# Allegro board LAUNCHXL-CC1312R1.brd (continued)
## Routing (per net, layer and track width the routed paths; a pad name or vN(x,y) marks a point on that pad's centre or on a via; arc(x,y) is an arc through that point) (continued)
VBUS_DET: length 5
  TOP w0.15: R93.1 10.25,84.05 10.27,84.07 R92.1 10.23,84.24 v1(9.86,84.24) ; U5.12 v1(9.65,86.84)
  L3 w0.15: v1(9.86,84.24) 9.86,86.63 9.66,86.84 v1(9.65,86.84)
VDDC: length 16.2
  TOP w0.2: C45.1 2.25,92.25 C44.1 C43.1 2.45,94.6 U5.115 6.5,94.6 8.85,96.95 U5.87
VDDR: length 26.6
  TOP w0.3: U1.45 C19.1 24.15,50.65 v1(24.15,50.38) ; v1(24.2,48.9) C20.1 24.75,48.91 25.2,49.36 25.21,49.36 25.3,49.45 U1.48
  TOP w0.6: v1(26.75,61.2) v1(27.47,61.2) 27.47,60.4 C18.1 28.05,60.25 L10.2
  L3 w0.6: v1(24.2,48.9) 24.2,50.32 v1(24.15,50.38) 22.57,50.38 22.15,50.8 22.15,57.89 22.91,58.65 24.26,58.65 24.67,59.06 24.67,59.86 25.31,60.5 26.9,60.5 26.98,60.57 27.01,60.57 27.38,60.94 27.38,60.97 27.47,61.07 v1(27.47,61.2) v1(26.75,61.2)
VDDS: length 36.4
  TOP w0.3: U1.34 27.67,56.9 C17.1 C16.1 v1(25.3,57.15) ; U1.22 33.9,53.95 C14.1 33.95,54.25 v1(34.15,54.45) ; v1(33.35,48.85) 34.15,48.85 C12.1 34.24,48.75 33.79,49.2 33.79,49.21 33.55,49.45 U1.13 ; v1(24.02,52.22) 24.45,51.8 C15.1 24.45,51.6 24.99,51.6 25.14,51.45 U1.44 ; R1.2 v1(24.19,56.37)
  TOP w0.6: FL1.1 v1(24.15,57) 24.15,56.41
  L3 w0.3: 32.79,54.65 32.99,54.45 v1(34.15,54.45)
  L3 w0.6: 26.11,55.35 32.09,55.35 32.79,54.65 32.79,49.41 v1(33.35,48.85) ; 26.11,55.35 25.21,55.35 v1(24.19,56.37) 24.19,56.96 v1(24.15,57) 24.3,57.15 v1(25.3,57.15) ; 26.11,55.35 26.21,55.25 26.21,52.65 25.78,52.22 v1(24.02,52.22)
BP_RESET: length 16.8
  TOP w0.15: J2.11 48.45,56.84 48.45,71.14 48.61,71.3 R52.1
DCDC_SW: length 2.3
  TOP w0.3: L10.1 28.17,56.97 U1.33
DIO1: length 26
  TOP w0.15: v1(30.17,47.2) 29.89,47.49 29.71,47.49 29.17,48.02 U1.6
  BOTTOM w0.15: v1(30.17,47.2) 28.57,48.8 26.9,48.8 26.18,49.52 23.32,49.52 22.55,48.75 20.95,48.75 20.6,48.4 15.14,48.4 12.34,45.6 J1.20
DIO4_SCL: length 110.6
  TOP w0.15: U1.9 30.67,48.32 31.63,47.37 42,47.37 46.16,51.54 46.16,66.31 45.77,66.7 34.45,66.7 25.65,75.5 9.6,75.5 3.15,69.05 3.15,50.29 5.3,48.14 J1.17 5,46.81 5,45.55 R2.1
DIO5_SDA: length 110
  TOP w0.15: R3.1 4.29,43.64 4.37,43.64 J1.19 7.65,46.92 7.65,48.75 7,49.4 5.55,49.4 3.45,51.5 3.45,68.93 9.72,75.2 25.35,75.2 34.15,66.4 45.6,66.4 45.75,66.25 45.75,51.55 41.87,47.67 31.83,47.67 31.17,48.33 U1.10
DIO6_RLED: length 84.5
  TOP w0.15: U1.11 31.67,48.33 32.03,47.97 41.75,47.97 45.38,51.6 45.38,64.85 45.32,64.9 v1(45.32,65.3) ; v1(18.93,65.25) 19.21,65.53 v1(30.01,65.53)
  L3 w0.15: v1(18.93,65.25) 18.93,54.22 18.08,53.38 17.32,53.38 15.59,51.64 P6.2 ; v1(30.01,65.53) 29.72,65.25 29.72,63.59 29.97,63.35 34.87,63.35 36.32,64.8 41.12,64.8 41.62,65.3 v1(45.32,65.3) 45.94,65.92 J2.3
DIO7_GLED: length 79.2
  TOP w0.15: v1(44.8,65.9) 44.8,64.95 45.07,64.68 45.07,51.72 41.62,48.27 33,48.27 32.53,48.75 U1.12 ; v1(19.95,63.85) 20.23,64.13 29.83,64.13 v1(30.15,63.81)
  L3 w0.15: v1(30.15,63.81) 33.71,63.81 35.79,65.9 v1(44.8,65.9) 47.36,68.46 J2.1 ; P6.4 18.13,47.38 17.71,47.8 17.71,51.86 19.95,54.1 v1(19.95,63.85)
DIO8_MISO: length 36
  TOP w0.15: U4.2 44.35,40.68 44.62,40.95 v1(46.4,40.95) ; v1(44.65,52.16) v1(42.44,49.95) U1.14
  L3 w0.15: v1(46.4,40.95) 46.8,40.95 47.41,41.56 47.41,45.18 42.64,49.95 v1(42.44,49.95) ; J2.14 50.84,54.45 46.94,54.45 v1(44.65,52.16)
DIO9_MOSI: length 35.3
  TOP w0.15: U1.15 v1(40.99,50.45) 42.2,50.45 44.65,52.9 v1(44.65,57.05) ; U4.5 45.35,43.15 v1(45.5,43.3)
  L3 w0.15: v1(44.65,57.05) 50.78,57.05 J2.12 ; v1(40.99,50.45) 40.99,50.08 44.52,46.55 45.07,46.55 45.87,45.75 45.87,43.67 v1(45.5,43.3)
DIO10_SCLK: length 98.7
  TOP w0.15: U4.6 v1(44.85,44.25) ; J1.13 4.05,55.5 4.05,68.68 8.22,72.85 10.9,72.85 12.95,74.9 25.22,74.9 34.02,66.1 43.3,66.1 44.5,64.9 44.5,57.6 44.22,57.32 44.22,52.93 42.25,50.95 v1(39.83,50.95) U1.16
  L3 w0.15: v1(39.83,50.95) 39.83,49.57 43.1,46.3 43.92,46.3 44.85,45.37 v1(44.85,44.25)
DIO11_CS: length 29.5
  TOP w0.15: v1(43.85,62.25) 43.85,53.3 42,51.45 U1.17
  L3 w0.15: J2.6 50.79,62.1 44.4,62.1 44.25,62.25 v1(43.85,62.25)
DIO12: length 31.3
  TOP w0.15: U1.18 41.9,51.95 43.35,53.4 43.35,64.25 v1(43.8,64.7)
  L3 w0.15: J2.4 51.35,65.19 50.75,65.19 50.26,64.7 v1(43.8,64.7)
DIO13_BTN1: length 73.7
  TOP w0.15: R56.2 6.74,73.5 7.57,74.34 v1(7.63,74.34) ; U1.19 41.6,52.45 v1(42.5,53.35) 43,53.85 43,65.45 42.65,65.8 33.9,65.8 25.85,73.85 v1(14.9,73.85)
  L3 w0.15: v1(42.5,53.35) 44.35,51.5 45.28,51.5 45.73,51.95 50.8,51.95 J2.16 ; v1(14.9,73.85) 14.5,73.85 14.01,74.34 v1(7.63,74.34)
DIO14_BTN2: length 46
  TOP w0.15: J2.18 54.39,48.14 56.42,50.17 R55.2 ; U1.20 v1(41.43,52.95)
  L3 w0.15: J2.18 50.76,49.45 45.52,49.45 42.02,52.95 v1(41.43,52.95)
DIO15: length 22.5
  TOP w0.15: U1.21 v1(40.15,53.45)
  L3 w0.15: v1(40.15,53.45) 42.82,50.78 43.39,50.78 46.31,47.86 46.31,47.85 47.07,47.85 47.07,47.85 48.03,46.9 50.77,46.9 J2.20
DIO16_TDO: length 45.5
  TOP w0.15: R48.2 36.67,70.97 v1(36.67,71.7) ; U1.26 31.67,64.82 31.67,64.83 v1(31.67,65.45) ; P4.6 31.73,74.12 33,72.85 33,71.95 v1(33.95,71) ; CR8.5 39.25,75.7 v1(43.45,75.7) 43.73,75.7 44.09,76.06 P5.6
  L3 w0.15: v1(31.67,65.45) 31.67,65.85 31.67,65.86 31.67,69.5 33.18,71 v1(33.95,71) 35.97,71 v1(36.67,71.7)
  BOTTOM w0.15: v1(43.45,75.7) 43.45,75 42.95,74.5 38.1,74.5 36.67,73.07 v1(36.67,71.7)
DIO17_TDI: length 42.7
  TOP w0.15: v1(44.71,75.8) 45.36,76.45 P5.8 ; CR8.3 39.05,73.45 v1(38.95,73.35) ; P4.4 34.27,72.68 v1(35.2,71.75) R49.2 ; U1.27 v1(31.17,66.3)
  L3 w0.15: v1(31.17,66.3) 31.17,70.92 32.01,71.75 v1(35.2,71.75) 35.85,72.4 38,72.4 v1(38.95,73.35)
  BOTTOM w0.15: v1(38.95,73.35) 39.23,73.63 43.72,73.63 43.72,73.62 44.7,74.6 44.7,75.39 44.71,75.4 v1(44.71,75.8)
DIO19_CTS: length 25
  TOP w0.15: v1(30.17,60.79) U1.29
  L3 w0.15: J2.7 48.5,60.84 47.94,61.4 30.78,61.4 v1(30.17,60.79)
DIO20_FLASH_CS: length 61.1
  TOP w0.15: U4.1 42.9,40.25 R11.2 v1(42.15,40.1) ; v1(29.63,61.75) 29.63,60.47 29.85,60.25 29.85,56.57 29.67,56.4 U1.30
  L3 w0.15: J2.5 48.5,63.38 48.02,62.9 30.78,62.9 v1(29.63,61.75) 29.75,61.63 29.75,60 30.03,59.72 30.03,57.75 30.43,57.35 35.99,57.35 37.47,55.87 37.47,50.32 42.34,45.45 42.87,45.45 43.95,44.37 43.95,42.85 43.6,42.5 42.51,42.5 42.15,42.14 v1(42.15,40.1)
DIO21: length 62.1
  TOP w0.15: v1(29.23,56.57) 29.17,56.52 U1.31 ; v1(10.7,73.35) 8.3,73.35 3.75,68.8 3.75,53.26 J1.15
  L3 w0.15: v1(29.23,56.57) 29.23,56.98 29.38,57.13 29.38,61.16 29.2,61.34 29.2,68.44 25.84,71.8 v1(25.15,71.8)
  BOTTOM w0.15: v1(25.15,71.8) 24.5,71.8 23.8,71.1 12.95,71.1 v1(10.7,73.35)
DIO22: length 50.8
  TOP w0.15: J1.9 4.35,60.28 4.35,68.55 8.2,72.4 v1(9.95,72.4) ; U1.32 v1(28.67,56.47)
  L3 w0.15: v1(28.67,56.47) 28.67,56.78 28.35,57.1 28.35,67.66 v1(26.39,69.62)
  BOTTOM w0.15: v1(26.39,69.62) 12.72,69.62 v1(9.95,72.4)
DIO23_ANALOG: length 25.3
  TOP w0.15: U1.36 25.35,55.65 24.5,54.8 19.55,54.8 v1(10.15,64.2)
  L3 w0.15: v1(10.15,64.2) 9.7,64.65 7.6,64.65 J1.3
DIO24_ANALOG: length 20.4
  TOP w0.15: v1(18.3,54.6) 18.32,54.6 18.42,54.5 24.67,54.5 25.12,54.95 U1.37
  L3 w0.15: v1(18.3,54.6) 17.9,54.6 17.8,54.5 7.59,54.5 J1.11
DIO25_ANALOG: length 21.2
  TOP w0.15: J1.6 9.6,62.65 9.6,62.4 17.82,54.18 24.97,54.18 25.25,54.45 U1.38
DIO26_ANALOG: length 20
  TOP w0.15: J1.8 9.6,60.11 10.09,60.11 16.35,53.85 25.22,53.85 25.32,53.95 U1.39
DIO27_ANALOG: length 19.1
  TOP w0.15: U1.40 25.32,53.45 25.22,53.55 14.65,53.55 9.9,58.3 J1.10
DIO28_ANALOG: length 18.3
  TOP w0.15: J1.12 10.99,55.76 13.5,53.25 24.79,53.25 25.09,52.95 U1.41
DIO29_ANALOG: length 17.4
  TOP w0.15: J1.14 9.9,53.22 10.17,52.95 24.67,52.95 25.17,52.45 U1.42
DIO30/TCXO_VCC: length 8.1
  TOP w0.15: U1.43 25.17,51.95 24.47,52.65 19.75,52.65 19.35,52.25 R9.1 R8.2
DIO30_ANALOG: length 9.3
  TOP w0.15: R9.2 15.45,52.25 13.88,50.68 J1.16
ET_1V8: length 6.8
  TOP w0.3: U35.1 43.5,105.95 43.35,105.8 42.41,105.8 42.15,105.54 C128.1 42.1,104.95 C159.1 C158.1 39.4,104.75 U43.5
ET_3V3: length 52.6
  TOP w0.15: 44.69,100.7 44.69,100.04 44.25,99.6 U37.3
  TOP w0.3: C141.1 56.39,100.15 56.18,99.94 55.25,99.94 U41.5 55.7,100.41 C142.1 ; U42.4 U42.3 35.1,100.5 35.15,100.5 35.15,100.75 34.95,100.95 U42.4 ; U42.4 34.9,101.22 34.23,101.89 34.23,101.9 33.79,102.35 R132.2 33.75,102.37 C153.1 ; 44.69,100.7 44.69,101.41 C126.2 v1(45.76,101.9) ; 55.55,103.95 U40.2
  TOP w0.6: 38.6,101.2 C155.1 37.2,101.25 C154.1 35.2,101.25 U42.4 ; 38.6,101.2 38.25,101.55 v1(37.95,101.55) ; 38.6,101.2 C156.1 v1(41,101.1) ; FL5.1 35.15,111 FL6.2 35.19,108.81 v1(35.19,107.8) ; 55.55,103.95 U40.1 55.55,101.85 C142.1 v1(56.95,101.7)
  L3 w0.3: 45.79,102.5 45.76,102.48 v1(45.76,101.9)
  L3 w0.6: v1(41,101.1) 41.78,101.1 43.18,102.5 47.65,102.5 48.55,101.6 52.46,101.6 53.35,102.49 53.35,102.5 56.15,102.5 v1(56.95,101.7) ; v1(37.95,101.55) 37.95,107.08 37.23,107.8 v1(35.19,107.8)
ET_5V0: length 6.1
  TOP w0.3: FL3.1 40.05,92.85 C167.1 ; C168.1 39.97,91.52 C125.2 41.25,91.57 U36.7
  TOP w0.6: FL3.1 C168.1
ET_AVDD: length 22.6
  TOP w0.3: v1(49.19,103.85) 49.35,103.85 R98.1 ; 40.88,107.6 41.28,108 U35.32 ; U35.6 46,105.3 C120.1 46.3,104.95 v1(45.9,104.55)
  TOP w0.6: v1(42.23,106.95) 41.53,106.95 40.88,107.6 C119.1 39.85,107.6 C121.1 39.05,107.55 37.75,108.85 FL6.1 ; C122.1 49.25,103.79 v1(49.19,103.85)
  L3 w0.3: 47.27,104.64 47.18,104.55 v1(45.9,104.55)
  L3 w0.6: v1(42.23,106.95) 45.56,106.95 47.27,105.24 47.27,104.64 48.06,103.85 v1(49.19,103.85)
ET_BYPASS: length 60.8
  TOP w0.15: v1(12.3,102.15) 12.3,102.25 12.45,102.4 U5.78
  TOP w0.2: U33.8 51.3,87.45 v1(51.1,87.25) ; v1(55.84,88.25) 55.54,87.95 U33.4
  L3 w0.2: v1(55.84,88.25) 54.72,88.25 54.27,87.8 52.91,87.8 52.36,87.25 v1(51.1,87.25)
  BOTTOM w0.15: v1(12.3,102.15) 12.9,101.55 12.9,100.55 14.5,98.95 26.8,98.95 28.3,97.45 28.3,92.35 29,91.65 31.5,91.65 32.8,92.95 37.1,92.95 37.35,92.7 37.35,88.05 37.95,87.45 37.95,87.4 38.1,87.25 v1(51.1,87.25)
ET_CAL0: length 25.7
  TOP w0.15: R129.1 v1(32.85,96.95) ; U5.74 v1(14.05,102)
  TOP w0.2: U39.13 32.45,95.9 R129.1
  BOTTOM w0.15: v1(32.85,96.95) 32.4,96.95 32.2,97.15 32.2,99.3 31.85,99.65 30.4,99.65 28.97,101.07 14.52,101.07 14.05,101.55 v1(14.05,102)
ET_CAL1: length 27.9
  TOP w0.15: R128.1 30.2,92.15 30.05,92.3 30.05,92.43 v1(30.12,92.5) ; U5.73 14.45,102.5 14.6,102.35 14.6,101.25 14.6,101.25 v1(14.6,100.55)
  TOP w0.2: R128.1 30.65,93.15 30.9,93.4 U39.5
  BOTTOM w0.15: v1(14.6,100.55) 15,100.15 28.65,100.15 29.5,99.3 29.5,93.12 v1(30.12,92.5)
ET_CAL2: length 22
  TOP w0.15: U5.23 14.05,89.1 v1(14.2,89.25) ; v1(31.5,90.9) 31.95,91.35 R127.1
  TOP w0.2: R127.1 32.05,92.2 U39.6
  BOTTOM w0.15: v1(31.5,90.9) 30.85,90.9 30.3,90.35 19.75,90.35 18.65,89.25 v1(14.2,89.25)
ET_CALIBRATE: length 31.6
  TOP w0.15: U5.77 12.85,101.9 v1(11.95,101) ; U38.4 v1(31.3,90.2) 31,90.5 29.7,90.5 v1(29.25,90.95)
  BOTTOM w0.15: v1(11.95,101) 11.95,99.9 14,97.85 26.6,97.85 27.6,96.85 27.6,92.05 28.7,90.95 v1(29.25,90.95)
ET_DVDD: length 41.7
  TOP w0.3: 39.05,110.65 C117.1 ; 39.05,110.65 C116.1 40.88,110.65 41.03,110.5 U35.27 ; 39.05,110.65 39.4,110.3 R114.1 ; R119.1 v1(51.9,109.95) ; R96.1 v1(49.3,114.65)
  TOP w0.6: v1(36.67,112.3) 37,111.97 FL5.2 37.15,110.9 C117.1 ; v1(34.08,116.05) FL4.1 37.4,116.05 Y6.1
  L3 w0.3: 50.07,114.6 50.02,114.65 v1(49.3,114.65)
  L3 w0.6: v1(51.9,109.95) 50.95,109.95 50.07,110.83 50.07,115.67 49.29,116.45 43.95,116.45 42.15,114.65 37,114.65 ; 37,114.65 36.67,114.32 v1(36.67,112.3) ; 37,114.65 37,115.48 36.43,116.05 v1(34.08,116.05)
ET_FB: length 45.1
  TOP w0.15: U45.4 50.35,86 v1(50.5,85.85)
  TOP w0.3: C169.2 37.1,114.03 37.1,113.6 ; R138.1 37.1,113.6 ; 37.1,113.6 v1(37.6,113.6) ; U45.3 U45.4
  BOTTOM w0.15: v1(37.6,113.6) 38.4,112.8 47.3,112.8 48.25,111.85 48.25,107.1 50.7,104.65 50.7,103.95 52.35,102.3 52.35,100.8 52.65,100.5 52.65,87.15 51.35,85.85 v1(50.5,85.85)
ET_PM2: length 48.6
  TOP w0.15: 13.25,103.3 13.25,102.5 13.45,102.3 v1(13.45,102.15) ; R96.2 47.21,114.65 v1(47,114.44) U35.17
  BOTTOM w0.15: v1(47,114.44) 46.26,115.18 26.57,115.18 22.4,111 22.4,106.45 21.88,105.93 21.88,102.88 21.6,102.6 19.75,102.6 19.1,101.95 17.75,101.95 17.6,101.8 15.38,101.8 15.1,102.08 15.1,102.7 14.95,102.85 13.75,102.85 13.45,102.55 v1(13.45,102.15)
ET_PN3: length 56.3
  TOP w0.15: U5.110 v1(2.6,96.6)
  TOP w0.3: R114.2 40.72,110 U35.28 43.25,110 v1(43.45,109.8)
  L3 w0.15: v1(26.5,102.6) 26.5,97.5 26.65,97.35 v1(26.65,96.95)
  BOTTOM w0.15: v1(43.45,109.8) 42.97,109.32 35.17,109.32 32.05,106.2 32.05,103.3 31.65,102.9 26.8,102.9 v1(26.5,102.6) ; v1(26.65,96.95) 22.32,96.95 21.65,96.27 2.92,96.27 v1(2.6,96.6)
ET_SSICLK: length 59.1
  TOP w0.15: v1(5.32,93.12) 4.8,92.6 U5.120 ; U35.22 v1(44.5,111.9)
  L3 w0.15: v1(22.32,94.52) 24.06,94.52 25.35,95.81 25.35,101.69 v1(24.99,102.05)
  BOTTOM w0.15: v1(22.32,94.52) 22.04,94.24 6.44,94.24 v1(5.32,93.12) ; v1(44.5,111.9) 44.02,111.43 32.02,111.43 30.92,110.33 29.52,110.33 28.9,110.95 26.8,110.95 26.62,110.77 26.62,104.98 26.35,104.7 25.5,104.7 24.99,104.19 v1(24.99,102.05)
ET_SSIDAT0: length 61.5
  TOP w0.15: U5.123 4.6,91.4 4.75,91.25 v1(5.25,91.25) ; U35.21 v1(45,113.95)
  L3 w0.15: v1(24.23,101.8) 24.47,101.56 v1(24.47,95.8)
  BOTTOM w0.15: v1(45,113.95) 44.77,114.18 36.42,114.18 34.75,112.5 26.95,112.5 25.45,111 25.45,108.5 24.75,107.8 24.75,104.65 24.23,104.13 v1(24.23,101.8) ; v1(24.47,95.8) 24.47,94.02 22.9,92.45 15.15,92.45 14.8,92.1 6.65,92.1 5.8,91.25 v1(5.25,91.25)
ET_SSIDAT1: length 61.5
  TOP w0.15: v1(5.1,90.45) 4.55,91 3.75,91 ; U35.20 v1(45.5,111.9)
  L3 w0.15: v1(26.05,96.3) 26.05,102.19 v1(25.59,102.65)
  BOTTOM w0.15: v1(25.59,102.65) 25.59,103.55 25.89,103.85 28.75,103.85 29.65,104.75 29.65,108.9 29.85,109.1 32.6,109.1 33.8,110.3 43.9,110.3 v1(45.5,111.9) ; v1(5.1,90.45) 10.25,90.45 11.15,91.35 19.15,91.35 19.45,91.65 25.25,91.65 26.05,92.45 v1(26.05,96.3)
ET_SSIFSS: length 62.9
  TOP w0.15: U35.19 v1(46,114.05) ; U5.121 4.7,92.2 4.8,92.3 v1(5.7,92.3)
  L3 w0.15: v1(23.7,96.25) v1(23.7,102.55)
  BOTTOM w0.15: v1(23.7,96.25) 23.7,94.45 22.42,93.18 6.58,93.18 v1(5.7,92.3) ; v1(23.7,102.55) 23.25,103 23.25,108.6 24.55,109.9 24.55,111.6 26.55,113.6 35.1,113.6 36.2,114.7 45.35,114.7 v1(46,114.05)
ET_VDD: length 61.3
  TOP w0.3: 32.4,112.15 U46.3
  TOP w0.6: 31.3,107.7 v1(31.3,107.67) ; 31.3,107.7 32.15,107.7 C174.1 33.7,109.25 C173.1 33.7,111.86 33.41,112.15 ; 31.3,107.7 CR14.1 ; C172.1 35.03,112.58 R151.2 33.67,112.15 33.41,112.15 ; 33.41,112.15 U46.4 32.4,112.15
  TOP w1: v1(31.3,107.67) v1(31.3,106.75)
  L3 w1: P10.1 49.85,85.15 49.35,85.65 49.35,90.31 53.23,94.19 53.23,95.8 52.83,96.2 50.35,96.2 49.6,96.95 42.63,96.95 39.83,99.75 39.83,102.29 40.19,102.65 40.19,109.29 38.78,110.7 34.43,110.7 33.08,109.35 33.04,109.35 31.36,107.67 v1(31.3,107.67) v1(31.3,106.75)
ET_VREF: length 17
  TOP w0.3: 51.47,107.28 C146.1 ; 51.47,107.28 50.75,108 C127.1 U35.9 ; 51.47,107.28 v1(51.47,108.35) ; 51.25,104.9 U40.6 ; v1(50.8,102.75) 50.8,100.1 50.25,99.55 R121.1
  TOP w0.6: 51.25,104.9 U40.5 51.25,106.9 C146.1
  L3 w0.3: v1(50.8,102.75) 51.47,103.42 v1(51.47,108.35)
IRSTN: length 24.6
  TOP w0.15: v1(19.69,105) 19.9,104.79 R20.2
  BOTTOM w0.15: P8.10 4.05,106.93 4.05,108.3 6.02,110.27 6.7,110.27 7.02,109.95 8.82,109.95 9.42,109.35 9.42,106.32 11.95,103.8 18.49,103.8 v1(19.69,105)
ITCK: length 13
  TOP w0.15: U5.100 2.85,100.6 2.59,100.86 1.44,100.86 v1(1.05,101.25)
  BOTTOM w0.15: P8.4 1.06,110.01 0.76,109.71 0.76,101.54 v1(1.05,101.25)
ITDI: length 14.3
  TOP w0.15: U5.98 2.9,101.4 2.5,101.8 v1(2.2,101.8)
  L3 w0.15: v1(3.63,103.95) 4.51,104.83 4.51,109.6 v1(5.31,110.4)
  BOTTOM w0.15: v1(5.31,110.4) 4.08,109.17 3.75,109.17 P8.8 ; v1(3.63,103.95) 2.2,102.52 v1(2.2,101.8)
ITDO: length 17.6
  TOP w0.15: v1(2.65,112.85) 2.05,113.45 1.35,113.45 0.85,112.95 0.85,103.55 1.25,103.15 2.5,103.15 2.8,102.85 2.8,102.1 3.1,101.8 U5.97
  BOTTOM w0.15: v1(2.65,112.85) 2.65,111.95 P8.6
ITMS: length 9.1
  TOP w0.15: 3.75,101 2.88,101 2.64,101.24 1.96,101.24 1.55,101.65 v1(1.55,102)
  BOTTOM w0.15: P8.2 1.45,107.47 1.3,107.32 1.3,102.65 1.55,102.4 v1(1.55,102)
LP_RESET: length 17.1
  TOP w0.15: R51.1 50.8,70.55 51.4,69.95 53.3,69.95 54,69.25 54,58.75 53.55,58.3 J2.10
LS_VDD: length 60.1
  TOP w0.15: v1(25.59,85.35) 25.1,84.86 C74.1 24.85,85.1 U10.2 ; U8.2 21,85.1 C70.1 21.1,85.01 v1(21.64,85.56) ; C72.1 28.95,85.1 U9.2
  TOP w0.2: v1(51.15,86.5) 51.15,86.57 51.53,86.95 U33.9 ; U33.3 v1(55.8,87.45)
  TOP w0.3: v1(30.5,84.35) 29.85,85 C72.1 29.05,85.35 v1(28.9,85.5) ; v1(38.51,86.2) 38.51,85.36 CR7.8
  TOP w0.6: P7.1 v1(45.71,88.34)
  L3 w0.15: v1(21.64,85.56) 21.93,85.84 25.1,85.84 v1(25.59,85.35) 25.99,85.75 28.25,85.75 28.5,85.5 v1(28.9,85.5)
  L3 w0.3: v1(30.5,84.35) 32.12,84.35 32.89,85.12 37.44,85.12 v1(38.51,86.2)
  L3 w0.6: v1(38.51,86.2) 38.76,85.95 44.31,85.95 ; 51.76,86.05 51.31,86.5 v1(51.15,86.5) ; 54.96,87.05 55.36,87.45 v1(55.8,87.45) ; P10.2 45.2,81.16 44.31,82.05 44.31,85.95 ; 44.31,85.95 44.46,85.95 45.71,87.2 v1(45.71,88.34)
  L3 w1: 53.31,85.55 54.46,85.55 54.96,86.05 54.96,87.05 ; 53.31,85.55 52.26,85.55 51.76,86.05 ; 53.31,85.55 53.41,85.45 53.41,83.27 51.3,81.16 P10.2
SW_VDD: length 59.6
  TOP w0.2: U39.14 32.05,96 C140.1 ; U33.1 55.45,86.45 C114.1
  TOP w0.3: 32.8,89.02 32.8,89.15 C139.1 ; 32.8,89.02 33.13,89.02 33.39,88.76 v1(33.39,88.15) ; 32.8,89.02 U38.1 ; v1(46.91,84.75) 46.98,84.82 54.77,84.82 55.6,85.65 C114.1 ; U45.5 49.35,87.3 48.88,87.78 C170.2 48.34,88.4 48.14,88.2 v1(47.51,88.2) ; C140.1 v1(31,96.25)
  TOP w0.6: v1(36.43,85.78) v1(36.43,86.46) 36.43,87.1 ; 36.43,87.1 C163.1 37,88.01 U44.5 38.74,88.66 C162.1 ; 36.43,87.1 R134.2
  L3 w0.3: v1(47.51,88.2) 46.91,88.2
  L3 w0.6: v1(33.95,91.7) 33.95,92.33 33.55,92.73 33.55,94.71 31.96,96.3 31.05,96.3 v1(31,96.25) ; v1(36.43,85.78) v1(36.43,86.46) ; v1(36.43,86.46) v1(34.11,86.46) 33.4,87.17 33.4,87.51 33.39,87.52 v1(33.39,88.15) ; v1(36.43,86.46) 36.43,87.59 37.99,89.15 42.4,89.15 43.35,90.1 46.31,90.1 46.91,89.5 v1(46.91,84.75)
  BOTTOM w0.6: v1(34.11,86.46) 34.11,87.09 34.43,87.4 34.43,91.22 v1(33.95,91.7)
TARGET_VDD: length 22.8
  TOP w0.3: U38.5 30.8,88.95 30.4,89.35 v1(30.4,89.5) v1(30.4,89.9)
  L3 w1: v1(30.4,89.9) 30.35,89.85 30.35,85.71 29.05,84.41 21.69,84.41 21.68,84.4 17.4,84.4 16.49,83.49 P4.17
TCXO_OUTPUT: length 1.2
  TOP w0.32: R7.1 20.49,47.26 C25.2
USB1V8: length 15
  TOP w0.15: C85.2 14.8,106.32 14.53,106.6 v1(14.45,106.6) 13.4,106.6 ; U15.15 v1(6.7,106.6) C84.1 ; 13.4,106.6 U15.26 ; 13.4,106.6 C83.1
  L3 w0.15: v1(14.45,106.6) 14.03,106.18 14.03,104.67 13.71,104.35 11.98,104.35 10.23,106.1 7.2,106.1 v1(6.7,106.6)
USB_VBUS: length 13.1
  TOP w0.3: v1(10.05,112.65) 10.16,112.54 10.5,112.54 CR6.6
  TOP w0.32: v1(15.95,110.6) 15.9,110.65 R154.1 ; U47.3 U47.4
  TOP w0.4: J6.1 v1(10.05,113.05) v1(10.05,112.65)
  TOP w0.6: C106.1 v1(13.5,111.6) ; 15.95,110.15 v1(15.95,110.6) U47.4
  L3 w0.15: v1(13.5,111.6) 13.53,111.6
  L3 w0.6: v1(15.95,110.1) v1(15.95,110.6) 14.53,110.6 13.13,112 10.47,112 10.05,112.42 v1(10.05,112.65) v1(10.05,113.05)
USBA1V8: length 3.2
  TOP w0.15: 14.95,108.76 C86.2 14.52,108.35 13.65,108.35 13.4,108.1 C87.1 13.2,108.1 U15.29
USBCLK: length 7.8
  TOP w0.15: U5.92 6.85,104.25 6.63,104.48 5.67,104.48 4.61,105.54 4.61,106.68 5.03,107.1 U15.14
USBD0: length 2.2
  TOP w0.15: U5.81 11.25,104.35 11.6,104.7 U15.24
USBD1: length 2.2
  TOP w0.15: U5.82 10.85,104.37 11.1,104.62 U15.23
USBD2: length 2.2
  TOP w0.15: U15.22 10.6,104.55 10.45,104.4 U5.83
USBD3: length 2.1
  TOP w0.15: U5.84 10.05,104.5 10.1,104.55 U15.21
USBD4: length 2.1
  TOP w0.15: U5.85 9.65,104.5 9.6,104.55 U15.20
USBD5: length 2.2
  TOP w0.15: U5.86 9.25,104.4 9.1,104.55 U15.19
USBD6: length 11.3
  TOP w0.15: U5.106 7.25,98.2 7.76,98.71 7.76,100.21 v1(8.05,100.5) ; v1(8.6,104.55) U15.18
  BOTTOM w0.15: v1(8.6,104.55) 8.6,101.05 v1(8.05,100.5)
USBD7: length 10.8
  TOP w0.15: U5.105 6.15,98.6 6.15,98.6 6.75,98.6 v1(7.05,98.9) ; U15.17 8.1,104.7 7.95,104.55 v1(7.67,104.55)
  BOTTOM w0.15: v1(7.67,104.55) 6.75,103.63 6.75,100.3 7.05,100 v1(7.05,98.9)
USBDIR: length 12.6
  TOP w0.15: v1(5.85,99.03) 5.82,99 U5.104 ; U15.12 6.4,108.1 6.37,108.07 v1(6.33,108.07)
  BOTTOM w0.15: v1(5.85,99.03) 5.85,100.3 5.62,100.52 5.62,107.37 v1(6.33,108.07)
USBDM: length 9.3
  TOP w0.15: CR6.5 11.2,112.6 v1(10.85,112.95) 10.7,113.1 J6.2 ; U15.8 7.62,110.3 v1(7.47,110.45)
  L3 w0.15: v1(7.47,110.45) 7.47,112.62 8.59,113.75 10.68,113.75 10.83,113.6 10.83,112.97 v1(10.85,112.95)
USBDP: length 12.3
  TOP w0.15: U15.7 8.6,110.93 8.33,111.2 v1(6.91,111.2) ; CR6.4 11.7,112.8 v1(11.5,113) 11.35,113.15 J6.3
  L3 w0.15: v1(11.5,113) 11.5,114 11.35,114.15 7.91,114.15 7.03,113.27 7.03,111.5 6.91,111.38 v1(6.91,111.2)
USBNXT: length 14.6
  TOP w0.15: v1(5.35,99.7) 5.05,99.4 U5.103 ; U15.11 7.09,108.6 6.39,109.3 v1(5.65,109.3)
  BOTTOM w0.15: v1(5.65,109.3) 4.4,108.05 4.4,100.1 4.8,99.7 v1(5.35,99.7)
USBSTP: length 5.3
  TOP w0.15: U5.91 v1(7.25,105.25) ; v1(6.65,107.52) 6.67,107.52 6.75,107.6 U15.13
  BOTTOM w0.15: v1(7.25,105.25) 7.25,106.93 v1(6.65,107.52)
VCM: length 18.9
  TOP w0.3: v1(51.7,100.25) 52,99.95 U41.1 ; v1(47.39,95.3) 47.39,95.94 R109.2 46.7,95.95 R100.1 ; v1(49.1,98.17) 49.12,98.2 R111.2 ; v1(55.83,97.1) R131.1
  L3 w0.3: 52.35,98.17 52.95,98.77 U41.1 52.65,100.25 v1(51.7,100.25) ; 52.35,98.17 54.76,98.17 v1(55.83,97.1) ; 52.35,98.17 v1(49.1,98.17)
  BOTTOM w0.3: v1(47.39,95.3) 47.39,96.46 v1(49.1,98.17)
WMCU_RESET: length 70
  TOP w0.15: R51.2 R52.2 49.31,75.5 47.47,77.33 ; v1(37.99,73.47) 38.55,74.03 CR8.2 ; 47.47,77.33 47.21,77.6 P5.10 ; 47.47,77.33 v1(47.47,77.32) ; v1(20.95,66.95) 21.2,67.2 24.75,67.2 v1(24.95,67.4) ; v1(21.45,55.5) C52.1 22.25,55.45 R1.1 24.3,55.45 25.2,56.35 27.05,56.35 27.17,56.22 U1.35
  L3 w0.15: v1(24.95,67.4) 24.95,70.85 24.11,71.69 v1(24.11,72.81) 24.77,73.47 v1(37.99,73.47) ; v1(21.45,55.5) 21.37,55.5 20.95,55.92 v1(20.95,66.95)
  BOTTOM w0.15: v1(47.47,77.32) 47.47,76.03 44.1,72.65 38.35,72.65 37.99,73.01 v1(37.99,73.47) ; v1(24.11,72.81) P4.12
WMCU_RXD: length 95.4
  TOP w0.15: U1.7 29.67,48.1 29.99,47.78 30.21,47.78 31.23,46.77 42.25,46.77 46.81,51.34 46.81,66.51 46.02,67.3 35.15,67.3 26.63,75.81 19.53,75.81 19.03,76.32 P4.16 ; v1(13.71,73.75) 13.2,73.75 10.5,71.05 10.5,67.95 9.95,67.4 6,67.4 5.05,66.45 5.05,64.66 J1.5
  BOTTOM w0.15: P4.16 19.03,77.59 19.05,77.57 19.05,76.3 17.39,74.65 14.6,74.65 v1(13.71,73.75)
WMCU_SWO: length 47.1
  TOP w0.15: v1(30.68,66.9) v1(30.68,59.7) 30.67,59.69 U1.28 ; v1(34.95,72.7) 34.95,76.76 P4.2
  L3 w0.15: v1(30.68,59.7) 46.7,59.7 48.1,58.3 J2.9 ; v1(34.95,72.7) 31.24,72.7 30.68,72.14 v1(30.68,66.9)
WMCU_TCK: length 49.4
  TOP w0.15: v1(39.65,79.45) 42.7,79.45 42.82,79.33 P5.4 ; CR8.6 38.55,76.5 38.66,76.61 39.38,76.61 v1(39.65,76.34) v1(39.67,76.32) ; v1(38.11,71.65) 38.1,71.64 R47.2 ; U1.25 v1(32.17,64.7)
  L3 w0.15: v1(32.17,64.7) 32.17,68.56 33.87,70.25 36.71,70.25 v1(38.11,71.65) 38.65,71.65 39.55,72.55 39.55,76.25 v1(39.65,76.34) v1(39.67,76.32)
  BOTTOM w0.15: v1(39.65,79.45) v1(39.65,76.34) 39.41,76.1 29.35,76.1 29.19,76.26 P4.8
WMCU_TMS: length 48
  TOP w0.15: v1(40.19,71.72) 40.19,71.57 39.57,70.95 R46.2 ; v1(40.6,77.55) 40.65,77.6 ; 40.65,77.6 38.8,77.6 38.05,76.85 CR8.7 37.3,75.9 v1(36.75,75.35) ; 40.65,77.6 P5.2 ; U1.24 v1(32.88,64.55)
  L3 w0.15: v1(32.88,64.55) 32.88,67.85 34.57,69.55 38.02,69.55 v1(40.19,71.72) 40.6,72.13 v1(40.6,77.55)
  BOTTOM w0.15: P4.10 26.65,76.45 27.75,75.35 v1(36.75,75.35)
WMCU_TXD: length 96.1
  TOP w0.15: v1(23.4,74.35) 13.1,74.35 10.65,71.9 8.12,71.9 4.65,68.43 4.65,62.52 J1.7 ; v1(27.1,74.7) 34.8,67 45.9,67 46.51,66.38 46.51,51.47 42.12,47.07 31.35,47.07 30.17,48.25 U1.8
  L3 w0.15: v1(23.4,74.35) 23.75,74.7 v1(27.1,74.7)
  BOTTOM w0.15: P4.14 21.57,74.81 22.03,74.35 v1(23.4,74.35)
WMCU_VDD: length 189.7
  TOP w0.3: v1(43.1,44) 43.43,43.67 R60.2 ; CR8.8 37.55,75.15 37,74.6 v1(37,74.45) ; 2.7,43.25 v1(2.1,43.84) ; 2.7,43.25 3.3,42.65 R3.2 ; 2.7,43.25 R2.2 2.7,43.25 ; R59.2 42.8,39.15 R11.1 41.75,39.2 v1(41.45,39.5) R12.2
  TOP w0.6: P5.1 v1(41.55,71.8)
  TOP w1: v1(22.9,61.45) v1(22.9,60.65) 22.9,60.55 FL1.2
  L3 w0.3: P1.1 52.03,35.4 50.75,35.4 49.83,36.32 49.83,38.05 48.38,39.5 v1(41.45,39.5) 41.44,39.5 40.99,39.95 40.99,43.19 41.8,44 v1(43.1,44) ; J1.1 4.25,68.46 1.54,65.75 1.54,44.4 v1(2.1,43.84)
  L3 w0.6: v1(41.55,71.8) 41.55,71.98 42.15,72.58 42.15,78.51 42.19,78.55 ; 21.59,76.18 21.47,76.3 ; v1(37,74.45) 37.38,74.45 37.83,74.9 37.83,75.98 37.51,76.3
  L3 w1: P4.18 16.49,76.88 17.07,76.3 ; J1.1 6.33,74.72 ; 6.33,74.72 7.91,76.3 17.07,76.3 ; 6.33,74.72 6.31,74.7 ; 17.07,76.3 37.51,76.3 39.76,78.55 49.78,78.55 P10.3 52.2,78.62 52.23,78.65 52.37,78.65 54.07,76.95 54.07,71.02 56.03,69.06 56.03,37.84 53.61,35.42 P1.1 ; 21.59,76.18 21.59,71.75 22.9,70.44 v1(22.9,61.45) v1(22.9,60.65)
XDS_RESET: length 11.5
  TOP w0.15: v1(23.19,87.5) 23.2,87.5 23.46,87.24 U10.6 23.46,84.85 23.61,84.7 U10.1 ; U5.40 21.15,92.2 R58.1 22.3,92.1 22.45,91.95 v1(22.45,89.9)
  BOTTOM w0.15: v1(23.19,87.5) 22.45,88.24 v1(22.45,89.9)
XDS_RESET_LS: length 58.3
  TOP w0.15: 40.63,82.68 v1(39.93,82.68) ; v1(21.53,114.98) R57.2 ; 37.05,84.6 36.91,84.46 v1(36.91,84.2) ; 37.05,84.6 35.12,84.6 34.75,84.23 v1(34.3,84.23) ; 37.05,84.6 CR7.2 ; v1(25.27,89.93) 24.4,90.8 24.4,94.09 v1(22.99,95.5) ; U10.15 23.46,82.99 v1(23.7,82.75) 24.11,82.34 P4.11
  L3 w0.15: v1(23.7,82.75) 24,83.05 31.54,83.05 32.71,84.23 v1(34.3,84.23) ; v1(21.53,114.98) 21.93,114.98 22.99,113.92 v1(22.99,95.5) ; v1(36.91,84.2) 37.19,83.91 38.7,83.91 v1(39.93,82.68)
  BOTTOM w0.15: v1(23.7,82.75) 23.7,86.75 25.56,88.61 25.56,89.64 v1(25.27,89.93)
XDS_RX: length 3.1
  TOP w0.15: U5.33 19.15,87.33 18.66,86.84 U8.8
XDS_RX_LS: length 9
  TOP w0.15: U8.13 18.66,83.41 18.95,83.12 R61.2 18.95,83.03 17.75,81.82 17.75,80.2 18.05,79.9 20.31,79.9 P4.13
XDS_SWO: length 7.2
  TOP w0.15: U5.25 14.85,88.75 15,88.9 17.9,88.9 18.05,88.75 18.05,86.3 U8.9
XDS_SWO_LS: length 26.7
  TOP w0.15: 35.6,83.69 35.95,83.69 36.81,82.83 P4.1 ; 35.6,83.69 v1(33.44,83.69) ; 35.6,83.69 35.57,83.66 R62.2 ; v1(17.45,82.21) 17.3,82.21 16.9,82.61 16.9,84.35 17.25,84.7 U8.12
  L3 w0.15: v1(33.44,83.69) 32.45,82.7 24.53,82.7 24.04,82.21 v1(17.45,82.21)
XDS_TCK: length 11.7
  TOP w0.15: v1(23.25,89.2) 23.53,89.49 26.82,89.49 27.46,88.84 U9.6 ; v1(20.65,89.2) 20.65,89.65 20.1,90.2 U5.35
  L3 w0.15: v1(23.25,89.2) v1(20.65,89.2)
XDS_TCK_LS: length 29
  TOP w0.15: U9.15 27.46,83.42 27.89,82.99 28.85,82.99 29.19,82.64 P4.7 ; v1(44.44,80.5) P7.4 44.44,83.83 43.67,84.6 CR7.6
  L3 w0.15: P4.7 30.44,79.91 38.89,79.91 39.28,80.3 43.84,80.3 44.04,80.5 v1(44.44,80.5)
XDS_TDI: length 10.5
  TOP w0.15: U9.7 27.06,87.44 25.95,88.55 23.05,88.55 20.2,91.4 U5.38
XDS_TDI_LS: length 25.9
  TOP w0.15: P4.3 32.78,82.65 31.2,82.65 30.5,81.95 30.5,80.5 29.9,79.9 28.5,79.9 27.95,80.45 27.95,82.5 27.06,83.39 U9.14 ; P7.8 41.9,81.05 41.7,80.85 v1(41.7,80.83) ; v1(37.75,83.2) CR7.3
  L3 w0.15: P4.3 35,81.89 35,82.95 35.25,83.2 v1(37.75,83.2) 40.12,80.83 v1(41.7,80.83)
XDS_TDO: length 9.9
  TOP w0.15: 19.15,91 20.18,91 23.17,88 25.2,88 26.25,86.95 26.25,86.1 U9.9
XDS_TDO_LS: length 29
  TOP w0.15: v1(25.59,82.05) 25.59,84.37 25.92,84.7 U9.12 ; P7.6 v1(43.17,80.88) 43.17,80.31 R63.2 ; v1(39.83,83.8) 39.53,84.1 CR7.5
  L3 w0.15: v1(25.59,82.05) 26.06,82.05 26.29,82.29 30.61,82.29 P4.5 34.12,83.55 34.59,83.55 35.66,84.62 39.01,84.62 v1(39.83,83.8) 42.79,83.8 43.19,83.4 43.19,80.9 v1(43.17,80.88)
XDS_TMS: length 6.1
  TOP w0.15: U5.36 20.15,90.6 22.66,88.09 U10.8
XDS_TMS_DIR: length 13.2
  TOP w0.15: U10.5 v1(23.86,87.55) ; v1(18.55,87.6) 18.55,88.68 18.02,89.2 14.8,89.2 14.45,88.85 U5.24
  L3 w0.15: v1(23.86,87.55) 23.42,87.99 18.94,87.99 v1(18.55,87.6)
XDS_TMS_LS: length 34.7
  TOP w0.15: U10.13 22.66,83.55 22.81,83.4 22.81,80.49 23.4,79.9 25.39,79.9 P4.9 ; 45.72,82.67 P7.2 ; CR7.7 v1(39.9,85.1)
  TOP w0.3: R65.2 46.2,83.17 P7.2 45.71,83.51 v1(46.35,84.15)
  BOTTOM w0.3: v1(46.35,84.15) 45.4,85.1 v1(39.9,85.1) 33.9,85.1 31.55,82.75 26.95,82.75 26.65,82.45 P4.9
XDS_TX: length 4.5
  TOP w0.15: U8.6 19.46,88.51 20.15,89.2 20.15,89.65 20,89.8 U5.34
XDS_TX_LS: length 3.1
  TOP w0.15: P4.15 19.03,82.28 19.46,82.71 U8.15
XDS_VDD: length 189.2
  TOP w0.15: U5.113 2.85,95.4 2.7,95.55 C3.1 ; v1(6.25,105.17) C78.1 6.63,105.7 7.03,106.1 U15.16 ; U5.69 16.05,104.5 C38.1 ; 8.07,111.8 v1(8.07,112.3) ; 8.07,111.8 R83.1 8.51,111.54 9.1,110.95 U15.6 ; 8.07,111.8 C80.1 ; U5.52 20.25,97 C39.1 U5.51 ; C6.1 13.35,105.25 12.99,105.25 12.9,105.16 12.9,105.2 ; C73.1 28.82,85.93 28.72,85.93 28.7,85.9 U9.4 U9.3 ; v1(2.23,99.62) C4.1 2.69,100.2 U5.101 ; 12.9,105.2 12.9,105.9 12.7,106.1 U15.25 ; 12.9,105.2 v1(12.9,105.2) 12.05,104.36 U5.79 ; R17.2 19,105.05 v1(18.75,105.3) ; U5.122 v1(4.85,91.8) ; 19.15,95 20.15,95 v1(20.25,94.9) ; v1(7.35,102.05) 7.65,102.35 U5.90 ; C71.1 20.85,85.9 U8.4 U8.3 ; U5.26 15.25,86.85 15.29,86.81 15.29,86.79 15.69,86.4 C2.1 16.05,86.75 U5.28 ; U15.31 13.05,109.1 ; 13.05,109.1 v1(13.3,109.36) ; 13.05,109.1 13.1,109.1 C79.1 13.2,108.6 U15.30 ; R58.2 21.25,91.19 20.64,91.8 U5.39 ; U5.16 v1(11.25,86.84) ; C75.1 25.05,85.9 U10.4 U10.3 ; U5.7 7.65,86.5 C42.1 8.05,86.7 U5.8
  TOP w0.2: v1(1.85,96.15) 1.85,96 2.19,95.66 C3.1 ; v1(24.63,109.15) 24.6,109.12 24.6,108.5 ; C47.1 24.23,103.42 R33.2 v1(24.23,104.93)
  TOP w0.3: C73.1 28.9,86.15 v1(28.4,86.65) ; C71.1 21.45,86.1 v1(21.7,86.35) ; C42.1 C7.1 6.45,86.4 v1(6.15,86.1) ; R18.2 v1(8.8,84.9) ; C40.1 21.15,96.6 ; 21.15,96.6 C39.1 ; 21.15,96.6 21.15,96.88 21.15,96.89 v1(21.15,97.08) ; 21.85,101.95 v1(22.3,101.95) ; 21.85,101.95 R27.1 ; 21.85,101.95 R39.1 ; 25.45,108.5 U7.3 ; C38.1 v1(15.95,105.1) ; R58.2 v1(21.73,91.18) ; R31.2 v1(18.75,105.3) ; C2.1 v1(15.7,85.8) ; C75.1 25.45,85.95 v1(25.7,86.2)
  TOP w0.6: 25.45,108.5 U7.4 C49.1 C113.1 v1(21.55,108.5) v1(21,108.5)
  L3 w0.15: 7.59,103.3 7.67,103.22 ; 7.37,102.05 v1(7.35,102.05) ; 6.25,103.32 6.23,103.3
  L3 w0.2: v1(24.63,109.15) 24.63,105.33 v1(24.23,104.93)
  L3 w0.3: v1(11.25,86.84) 11.25,88.15 ; v1(1.85,96.15) 1.85,95.97 2.27,95.55 3.59,95.55 3.75,95.39 ; v1(18.75,105.3) 17,105.3 16.95,105.25 ; 25.71,86.79 25.7,86.77 v1(25.7,86.2) ; 19.39,91.2 19.41,91.18 v1(21.73,91.18) ; v1(15.7,85.8) 15.7,88.12 15.67,88.15 ; v1(20.25,94.9) 19.39,94.9 ; 7.37,102.05 7.67,102.35 7.67,103.22 ; v1(8.8,84.9) 8.8,88.14 8.79,88.15 ; v1(6.25,105.17) 6.25,103.32 ; v1(15.95,105.1) 15.95,103.3 ; v1(22.3,101.95) 19.39,101.95 ; v1(8.07,112.3) 8.07,112.27 9.19,111.15 9.19,110.07 9.31,109.95 ; v1(21.7,86.35) 21.7,86.77 21.71,86.79 ; v1(21.15,97.08) 20.67,96.6 19.39,96.6 ; 3.75,102.58 2.74,102.58 1.82,103.5 1.82,105.48 v1(1.85,105.5)
  L3 w0.6: 12.91,107.25 12.9,107.24 v1(12.9,105.2) ; 12.91,107.25 14.95,107.25 16.2,108.5 16.95,108.5 ; 12.91,107.25 12.91,108.96 ; 17.55,88.15 7,88.15 6.91,88.06 ; 17.55,88.15 17.99,88.15 19.39,89.55 19.39,91.2 ; 17.55,88.15 17.55,87.21 17.97,86.79 28.26,86.79 v1(28.4,86.65) ; 16.95,108.5 v1(21,108.5) v1(21.55,108.5) ; 16.95,108.5 16.95,103.3 ; 3.75,91.8 3.75,89.5 5.19,88.06 6.91,88.06 ; 3.75,91.8 3.75,99.63 ; 3.75,91.8 3.76,91.8 v1(4.85,91.8) ; v1(6.15,86.1) 6.15,87.3 6.91,88.06 ; 9.31,109.95 12.03,109.95 12.91,109.07 12.91,108.96 ; 16.95,103.3 18.72,103.3 19.39,102.63 19.39,94.9 ; 16.95,103.3 4.47,103.3 3.75,102.58 3.75,99.63 ; v1(2.23,99.62) 3.74,99.62 3.75,99.63 ; 12.91,108.96 v1(13.3,109.36)
  BOTTOM w0.3: P8.1 1.85,106 v1(1.85,105.5)
N949215: length 9.6
  TOP w0.15: 20.8,103.4 R21.1 ; 20.8,103.4 R20.1 R17.1 ; 20.8,103.4 v1(21.2,103.4) ; U5.70 v1(15.65,102.24)
  BOTTOM w0.15: v1(15.65,102.24) 15.65,102.64 15.91,102.9 18.5,102.9 R17.1 v1(21.2,103.4)
N949243: length 2.1
  TOP w0.15: R30.1 21.04,99.7 20.54,100.2 U5.60
N949263: length 3.1
  TOP w0.2: R34.2 25.2,103.38 C47.2 25.15,103.42 R33.1 U7.5
N949375: length 2.3
  TOP w0.15: R28.2 21.01,98.85 20.06,99.8 U5.59
N949687: length 13.6
  TOP w0.15: C1.1 3.95,108.4 4.2,108.65 5.05,108.65 v1(5.35,108.35) ; U5.89 8.05,101.85 v1(7.85,101.65)
  BOTTOM w0.15: v1(7.85,101.65) 8.15,101.95 8.15,107.15 6.65,108.65 5.66,108.65 v1(5.35,108.35)
N949699: length 22
  TOP w0.15: U5.88 8.45,101.65 7.45,100.65 v1(7.2,100.65) ; v1(6.15,109.73) 3.52,109.73 2.5,110.75 Y3.1 1.85,110.2 C9.1
  BOTTOM w0.15: v1(7.2,100.65) 7.2,100.45 7.6,100.05 8.65,100.05 9.05,100.45 9.05,104.7 9.02,104.73 9.02,104.73 8.78,104.98 8.77,104.98 8.57,105.18 8.57,107.73 6.6,109.7 6.58,109.7 6.55,109.73 v1(6.15,109.73)
N950083: length 6.7
  TOP w0.15: U5.9 8.45,86.7 R18.1 8.95,86.2 C8.1 C50.1 9.99,84.91 10.2,84.7 11.93,84.7 U6.3
N951001: length 2.2
  TOP w0.15: U5.63 19.91,101.4 20.91,102.4 R39.2
N951013: length 1.9
  TOP w0.15: U5.61 R29.1
N951017: length 2
  TOP w0.15: 19.15,101 20.41,101 20.91,101.5 R27.2
N952443: length 2.4
  TOP w0.2: U5.68 16.45,104.05 16.85,104.45 C46.1 16.85,104.8 R31.1
N1004371: length 8.1
  TOP w0.15: U5.3 6.05,88.61 5.76,88.9 5.05,88.9 4.2,88.05 4.2,86.95 3.45,86.2 1.5,86.2 1.2,86.5 R23.2
N1004534: length 6.3
  TOP w0.15: U5.4 6.45,88.85 6.1,89.2 4.66,89.2 2.94,87.48 2.54,87.48 2.15,87.09 R25.2
N1014101: length 10
  TOP w0.15: U1.4 28.24,48.69 28.24,47.92 30.2,45.96 30.2,43.7 31,42.9 Y1.1 32.4,42.6 C41.1
N1014113: length 7.2
  TOP w0.15: U1.5 28.67,47.91 31.18,45.4 Y1.2 33.2,45.4 33.4,45.6 C51.1
N1017630: length 2.5
  TOP w0.3: R12.1 41.65,42.75 C30.1 43.28,42.75 43.38,42.65 U4.8
N1018954: length 2.1
  TOP w0.15: Y2.1 21.2,47.95 21.2,47.85 R5.2 20.6,48.45 C22.1
N1031635: length 6.8
  TOP w0.15: CR6.1 10.7,111.43 v1(10.5,111.23) ; v1(7.75,113.45) 7.35,113.45 7.2,113.3 R32.2
  BOTTOM w0.15: v1(10.5,111.23) 10.1,111.23 10.1,111.23 9.72,111.23 9.25,111.7 7.75,111.7 7.45,112 7.45,113.15 v1(7.75,113.45)
  vias: v1(7.11,115.2) v1(7.39,114.25)
N1105722: length 0.9
  TOP w0.15: 18.12,40.38 CR1.2
  TOP w0.3: R15.1 18.12,40.38
N1105771: length 0.9
  TOP w0.15: 15.57,40.38 CR2.2
  TOP w0.3: R14.1 15.57,40.38
N1105824: length 1.6
  TOP w0.3: P6.1 15.57,43.76 R14.2
N1106228: length 1.7
  TOP w0.15: 18.12,42.74 18.13,42.75
  TOP w0.3: R15.2 18.12,42.74 ; 18.13,42.75 P6.3
N1176548: length 29
  TOP w0.15: J2.15 48.27,50.68 47.75,51.2 47.75,67.3 46.8,68.25 38.5,68.25 38.1,68.65 R47.1
N1176568: length 31.4
  TOP w0.15: R48.1 36.67,69.35 38.12,67.9 46.4,67.9 47.45,66.85 47.45,50.22 J2.17
N1177007: length 35.1
  TOP w0.15: J2.19 47.15,47.98 47.15,66.6 46.15,67.6 36.97,67.6 35.22,69.35 R49.1
N1288065: length 3.5
  TOP w0.15: SW2.3 54.15,71.09 55.49,69.75 R55.1
N1288098: length 1.8
  TOP w0.15: SW1.4 4.5,72.78 5.22,73.5 R56.1
N1384129: length 1.2
  TOP w0.15: SW3.3 22.47,114.43 R57.1
N1409884: length 1.1
  TOP w0.15: U4.3 R59.1
N1409917: length 0.7
  TOP w0.3: U4.7 R60.1
N1553941: length 1.7
  TOP w0.15: R83.2 9.07,111.48 9.6,110.95 U15.5
N1579665: length 1.6
  TOP w0.15: R84.2 13.43,110.45 12.58,109.6 U15.32
N1580179: length 9.3
  TOP w0.15: R87.2 19.7,108.32 19.27,107.9 17.92,107.9 16.9,108.93 Y4.1 16.07,108.22 C88.2 15.65,108.21 14.89,107.45 13.08,107.45 12.93,107.6 U15.28
N1580186: length 11.7
  TOP w0.15: U15.27 15.05,107.1 15.51,106.63 15.64,106.63 v1(15.92,106.35)
  TOP w0.3: C89.2 20.17,106.4 v1(20.75,106.4) ; C89.2 R87.1 ; C89.2 20.13,106.4 19.05,106.4 Y4.3
  BOTTOM w0.15: v1(20.75,106.4) 20.35,106.4 20.3,106.35 v1(15.92,106.35)
N1644260: length 2.8
  TOP w0.15: U5.95 5.65,104.07 4.32,105.4 R90.2
N1644363: length 2
  TOP w0.15: R91.2 4.6,104.6 5.25,103.95 U5.96
N2070550: length 1.4
  TOP w0.15: C53.1 33.9,55.06 33.29,54.45 U1.23
N2071733: length 2.5
  TOP w0.3: U1.1 26.67,47.9 L12.2 26.48,47.03 C11.1 L11.1
N2072219: length 2.5
  TOP w0.3: U1.2 27.17,47.93 L12.1 L32.1 C21.1
N2074535: length 2.7
  TOP w0.2: L32.2 27.91,47.41 27.91,48.05 27.67,48.29 U1.3
  TOP w0.3: L32.2 28.32,46.33 C31.1
N2075216: length 2.4
  TOP w0.3: 26.9,44.88 C33.1 L33.1 ; 26.9,44.88 26.9,44.93 L11.2 ; 26.9,44.88 C21.2
N2075665: length 1.4
  TOP w0.3: L34.1 C34.1 L33.2
N2076038: length 8.8
  TOP w0.3: L34.2 C35.1
  TOP w0.32: C36.1 29.1,34.62 26.9,36.82 C35.1
N2078765: length 13.6
  TOP w0.32: J7.1 30.84,31.85 30.04,32.65 C37.2
N2082297: length 2.4
  TOP w0.32: Z63.1 Z62.1 Z61.1 Z60.2
N2239551: length 5.4
  TOP w0.15: U1.47 25.12,49.95 24.77,49.6 23.95,49.6 21.85,47.5 R7.2
N2239563: length 4.9
  TOP w0.15: R6.1 22.14,51.5 23.74,49.9 24.65,49.9 25.2,50.45 U1.46
N2245591: length 1.3
  TOP w0.32: Z63.2 A1.1
  vias: v1(10.3,11.55) v1(10.35,14.1) v1(10.4,5.95) v1(10.4,1.8) v1(10.45,17.95) v1(11.7,16.35) v1(11.75,4.6) v1(12.19,7.95) v1(12.4,12.9) v1(12.9,3.05) v1(13.45,17.95) v1(14.95,11.6) v1(15.15,6.65) v1(15.1,1.7) v1(17.2,16.55) v1(17.95,13) v1(18.05,8) v1(18.35,3.05) v1(20.15,18) v1(20.55,11.6) v1(20.5,1.7) v1(22.19,6.67) v1(22.7,16.67) v1(23.5,12.95) v1(23.8,3) v1(25.75,8.05) v1(26.15,1.6) v1(26.35,11.6) v1(26.5,18.05) v1(28.4,24.95) v1(28.4,19.7) v1(29.1,12.9) v1(29.75,22.5) v1(29.7,16.65) v1(29.95,6.65) v1(32.45,11.55) v1(32.7,7.95) v1(35.8,13) v1(37.35,6.7) v1(38.7,7.95) v1(39.35,11.67) v1(42.27,6.67) v1(42.6,13.05) v1(44.7,8) v1(45.35,11.67) v1(46.45,9.8) v1(47.65,13) v1(47.75,6.75)
N2266542: length 0.7
  TOP w0.32: C36.2 Z60.1
N3002303: length 17.7
  TOP w0.3: U34.6 U34.7 ; U34.7 46.5,117.7 ; U34.7 U34.8 ; v1(36.43,118.45) 36.43,117.93 36.35,117.85 ; 46.5,117.7 v1(46.5,118.25) ; 46.5,117.7 C115.1
  TOP w0.6: C118.1 35.2,117.75 FL4.2 37.7,117.85 Y6.4
  L3 w0.3: v1(46.5,118.25) 36.63,118.25 v1(36.43,118.45)
N3002611: length 13.6
  TOP w0.3: R107.1 52.8,93.5 51.85,92.55 R99.2 ; U33.2 v1(57.15,86.95)
  TOP w0.6: 56,93.5 R107.1
  TOP w1: v1(57.15,92.35) 56,93.5
  L3 w1: v1(57.15,92.35) v1(57.15,86.95)
N3002631: length 2.4
  TOP w0.3: Y6.3 40.59,118.2 U34.1
N3002671: length 0.5
  TOP w0.3: U34.2 U34.3
N3002679: length 3.1
  TOP w0.3: R94.2 43.5,116.15 44.05,116.7 U34.5
N3002683: length 1.6
  TOP w0.3: U35.24 R94.1
N3002707: length 48.9
  TOP w0.3: U33.7 51.45,87.95 v1(51.3,88.1) 50.87,88.1 50.5,87.73 50.5,86.9 50.2,86.6 48.95,86.6 48.25,87.3 U45.1 ; R108.2 52.77,90.6 R107.2 ; U38.3 31.8,89.45 31.9,89.55 v1(31.9,89.55)
  TOP w0.6: R107.2 54.95,90.55 v1(51.95,90.55)
  TOP w1: v1(50.87,94.1) 51.72,94.95 v1(55.11,94.95)
  L3 w1: v1(51.3,88.1) 51.95,88.75 v1(51.95,90.55) 54.11,90.55 55.11,91.55 v1(55.11,94.95) ; v1(50.87,94.1) 50.28,93.51 45.86,93.51 44.75,92.4 40.75,92.4 39.3,90.95 35.03,90.95 33.63,89.55 32.7,89.55 32.7,89.55 v1(31.9,89.55)
N3002889: length 7.7
  TOP w0.3: R95.2 41.65,101.6 41.86,101.39 41.86,97.69 42.1,97.45 R101.1 R102.2 43.45,96.6 C129.1
N3002897: length 2.5
  TOP w0.3: R95.1 R103.1 R104.2
N3003137: length 3.9
  TOP w0.3: 43.45,99.1 43.24,98.89 43.24,97.79 R102.1 C130.1 ; 43.45,99.1 U37.4 ; 43.45,99.1 42.75,99.1 C123.1
N3003145: length 3.6
  TOP w0.3: C123.2 42.93,100.6 U37.1 43.79,100.59 43.11,100.59 42.9,100.8 R103.2
N3003349: length 2.1
  TOP w0.15: U35.29 41.11,109.5 40.31,108.7 R97.1
N3003461: length 3.9
  TOP w0.3: U36.3 49.66,92.84 C132.1 ; C132.1 49.95,92.55 R99.1 ; C132.1 C124.2
N3003521: length 3.8
  TOP w0.15: R98.2 49.78,105.2 49.35,105.2 48.95,105.6 47.15,105.6 47,105.75 U35.8
N3003585: length 4.2
  TOP w0.3: U36.8 44.55,90.3 45.8,89.05 R137.1
N3003709: length 4.6
  TOP w0.3: R101.2 42.1,95.35 41.7,94.94 41.7,93.05 41.91,92.84 U36.6
N3003761: length 2.9
  TOP w0.3: U35.3 44.5,105.2 C131.1 44.1,104.8 R104.1
N3003773: length 2.1
  TOP w0.15: U35.23 44,114.2 44.37,114.58 R105.2
N3003833: length 4.1
  TOP w0.3: C132.2 50.03,91.55 R108.1 ; C132.2 C134.1 ; C132.2 49.69,91.57 U36.2
N3003845: length 3.8
  TOP w0.15: U37.7 46.18,99.6 v1(46.27,99.7)
  TOP w0.3: C133.1 48.2,99.35 v1(48.1,99.25) 48.2,99.15 R111.1
  L3 w0.3: v1(48.1,99.25) 47.65,99.7 46.75,99.7 46.75,99.7 v1(46.27,99.7)
N3003889: length 3.6
  TOP w0.3: R100.2 R106.2 44.35,95.52 44.35,94.45 44.01,94.11 U36.5
N3003929: length 3.9
  TOP w0.3: C130.2 R110.1 46.25,97.8 46.25,98.85 46,99.1 ; U37.6 46,99.1 ; 46,99.1 46.63,99.1 C135.1
N3003937: length 3
  TOP w0.3: 46.3,100.6 46.45,100.6 C135.2 ; 46.3,100.6 U37.9 ; 46.3,100.6 46.51,100.81 46.51,101.43 46.5,101.45 R112.2
N3003989: length 2.1
  TOP w0.15: C136.1 43.25,105 44,105.75 U35.2
N3004061: length 8.8
  TOP w0.3: C129.2 46.05,96.6 R110.2 R109.1 ; R109.1 47.49,96.94 47.49,100.29 47.7,100.5 R120.2 ; R109.1 R115.1
N3004137: length 2.8
  TOP w0.3: R113.1 45.3,104.9 C131.2 45,105.2 U35.4
N3004141: length 1.7
  TOP w0.15: U35.11 C137.1
N3004269: length 2.4
  TOP w0.3: R113.2 R112.1 R120.1
N3004289: length 2.4
  TOP w0.15: U35.25 41.47,111.5 40.95,112.02 40.95,112.55 40.75,112.75 C138.1
N3004389: length 2.6
  TOP w0.15: U35.7 46.5,105.63 46.97,105.16 46.97,104.8 47.27,104.5 R116.2
N3004561: length 1.9
  TOP w0.15: U35.16 49.02,111.5 49.52,112 R117.2
N3004593: length 1.7
  TOP w0.15: U35.15 R118.2
N3004681: length 1.9
  TOP w0.15: R119.2 49.68,109.5 U35.12
N3004851: length 9.6
  TOP w0.15: v1(32.2,94.1) 32.2,94.2 31.8,94.6 U39.2 ; v1(32.2,94.1) 32.45,94.1 32.75,93.8 U39.9 ; v1(32.2,94.1) 32.02,94.1 31.89,93.97 ; 31.89,93.97 31.72,93.8 U39.4 ; 31.89,93.97 32.01,94.1
  TOP w0.3: U38.2 32.3,89.24 32.35,89.29 32.35,89.34 32.47,89.46 v1(32.47,91)
  L3 w0.6: v1(32.47,91) 32.47,91.14 31.71,91.9 31.71,93.61 v1(32.2,94.1)
N3005293: length 3.3
  TOP w0.2: U39.1 31,95 30.5,95.5 C143.1 28.45,95.5 R123.2
N3005369: length 1.7
  TOP w0.3: R136.2 57.12,104.75 U40.3
N3005381: length 4.5
  TOP w0.3: U41.3 52.95,96.5 C147.1 ; U41.3 52.85,97.95 ; U41.3 R126.2 R121.2
N3005457: length 1.7
  TOP w0.3: U40.4 56.32,105.4 56.62,105.7 C145.1
N3005465: length 1.8
  TOP w0.3: C146.2 53.35,107.15 53.6,106.9 R122.2
N3005509: length 4.2
  TOP w0.2: U39.3 29.8,94.2 C144.1 27.55,93.9 R125.2
N3005629: length 1.5
  TOP w0.3: U41.4 56.67,98.05 R131.2
N3005723: length 2.2
  TOP w0.2: U39.8 C149.1 R130.1
N3011605: length 3.5
  TOP w0.3: U42.5 31.9,102.17 R133.2 31.82,102.35 R132.1 32.85,103.33 C153.2
N3011753: length 5.8
  TOP w0.3: 36.18,113.17 36.18,114.03 C169.1 ; 36.18,113.17 35.77,113.57 C172.2 34.17,113.57 R151.1 34.1,114.52 R152.2 34.11,114.55 33.51,115.15 U46.5 ; 36.18,113.17 R138.2
N3012529: length 2.7
  TOP w0.2: 35.32,88.23 34.95,87.86 R134.1 ; 35.32,88.23 U44.4 ; 35.32,88.23 R135.2
N3025885: length 1.4
  TOP w0.3: R137.2 47.65,89.9 U36.1
N3156339: length 1.4
  TOP w0.6: R153.1 FL3.2
N3157182: length 1.9
  TOP w0.15: 21.35,50.85 21.78,50.85 Y2.3 ; 21.35,50.85 R6.2 21.35,50.85 ; 21.35,50.85 21.25,50.85 C23.1
N3167465: length 5.2
  TOP w0.3: 18.55,111 U47.5
  TOP w0.5: 18.55,111 19.25,111 CR15.1 19.4,111.64 20.15,112.39 C109.1 C108.1 21.9,112.4 FL2.2
N3174121: length 4.3
  TOP w0.15: v1(12.2,113) 12,113.2 J6.4 ; CR6.2 11.2,111.3 v1(11.05,111.15)
  BOTTOM w0.15: v1(11.05,111.15) 11.05,111.55 11.5,112 11.95,112 12.2,112.25 v1(12.2,113)
N3220034: length 24.2
  TOP w0.15: J2.13 48.1,54.65 48.1,67.6 47,68.7 40.9,68.7 40.25,69.35 R46.1
N3261415: length 2.1
  TOP w0.3: 14.9,112 U47.2 ; 14.9,112 14.9,112.45 R155.2 ; 14.9,112 R154.2
N3263468: length 1.5
  TOP w0.3: C107.1 16.69,113.7 15.95,112.95 U47.1
N3266724: length 1.8
  TOP w0.2: R156.2 19.15,112.3 18.85,112 U47.7
N3270349: length 1.3
  TOP w0.15: R82.1 9.91,111.12 10.1,110.93 U15.4
N3291381: length 2.1
  TOP w0.32: C25.1 19.69,47.89 18.46,47.89 18.23,48.12 Y7.3
N3291400: length 1.8
  TOP w0.3: Y7.4 18.23,51.13 R8.1 C24.1
N10367920: length 1.2
  TOP w0.15: R25.1 CR5.2
N10368080: length 1.2
  TOP w0.15: CR4.2 R23.1

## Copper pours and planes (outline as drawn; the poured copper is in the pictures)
GND on TOP (solid shape): 9.45,79.1 0.95,79.1 0.65,80.1 0.45,81.3 0.45,84.1 9.45,84.1
GND on BOTTOM (solid shape): 9.45,79.1 0.95,79.1 0.65,80.1 0.45,81.3 0.45,84.1 9.45,84.1
GND on TOP: 0.45,114.1 0.45,117.84 0.73,118.52 1.41,118.8 6.45,118.8 6.45,117.6 6.55,117.6 6.55,114.1
GND on TOP: 39.95,39.25 39.95,33.4 44.2,33.4 44.2,26.65 23,26.65 23,39.25
GND on TOP, BOTTOM: 53.25,114.2 53.25,118.8 56.99,118.8 57.67,118.52 57.95,117.84 57.95,114.2
GND on BOTTOM: 0.45,26.55 0.45,68.5 0.71,70 1.44,71.34 2.65,74.7 1.57,78.1 1.5,78.18 1.44,78.26 1.25,78.52 1.07,78.8 0.61,79.91 0.45,81.1 0.45,81.29 0.45,81.3 0.45,117.84 0.73,118.52 1.41,118.8 6.45,118.8 6.45,117.6 8.05,117.6 8.05,115.5 9.95,115.5 9.95,117.6 12.75,117.6 12.75,115.5 14.65,115.5 14.65,117.6 16.25,117.6 16.25,118.8 56.99,118.8 57.67,118.52 57.95,117.84 57.95,117.6 57.95,84.8 57.95,81.1 57.85,80.3 57.79,80 57.81,80 57.48,79.09 56.96,78.26 55.75,74.8 56.96,71.34 57.69,70 57.95,68.5 57.95,26.55 ; 6 cut-outs
GND on BOTTOM: 0.45,114.3 0.45,117.84 0.73,118.52 1.41,118.8 5.05,118.8 5.05,114.3
GND on L2: 0.45,26.55 0.45,68.5 0.71,70 1.44,71.34 2.65,74.8 1.44,78.26 0.92,79.09 0.59,80 0.61,80 0.55,80.3 0.45,81.3 0.45,117.84 0.73,118.52 1.41,118.8 6.45,118.8 6.45,117.6 8.05,117.6 8.05,115.5 9.95,115.5 9.95,117.6 12.75,117.6 12.75,115.5 14.65,115.5 14.65,117.6 16.25,117.6 16.25,118.8 56.99,118.8 57.67,118.52 57.95,117.84 57.95,117.6 57.95,81.3 57.95,81.1 57.85,80.3 57.79,80 57.81,80 57.48,79.09 56.96,78.26 55.75,74.8 56.96,71.34 57.69,70 57.95,68.5 57.95,26.55 ; 2 cut-outs
GND on L3: 0.55,26.6 0.55,68.55 0.81,70.05 1.54,71.39 2.75,74.85 1.54,78.31 1.02,79.14 0.69,80.05 0.71,80.05 0.65,80.35 0.55,81.35 0.55,117.89 0.83,118.57 1.51,118.85 6.55,118.85 6.55,117.65 8.15,117.65 8.15,115.55 10.05,115.55 10.05,117.65 12.85,117.65 12.85,115.55 14.75,115.55 14.75,117.65 16.35,117.65 16.35,118.85 57.09,118.85 57.77,118.57 58.05,117.89 58.05,117.65 58.05,81.35 58.05,81.15 57.95,80.35 57.89,80.05 57.91,80.05 57.58,79.14 57.06,78.31 55.85,74.85 57.06,71.39 57.79,70.05 58.05,68.55 58.05,26.6 ; 20 cut-outs
VDDR on TOP: 27.8,59.7 27.8,61.5 25.8,61.5 25.8,60.9 26.8,60.9 26.8,59.7
VDDS on TOP: 23.45,58.5 23.45,56.65 25,56.65 25,58.5
(no net) on TOP: 57.69,70.05 57.95,68.55 57.95,39.18 57.95,26.65 44.2,26.65 44.2,33.4 39.95,33.4 39.95,39.25 23,39.25 23,26.65 0.45,26.65 0.45,68.55 0.71,70.05 1.44,71.39 2.65,74.85 1.44,78.31 0.71,79.65 0.45,81.15 0.45,117.89 0.73,118.57 1.41,118.85 6.45,118.85 6.45,117.65 8.05,117.65 8.05,115.55 9.95,115.55 9.95,117.65 12.75,117.65 12.75,115.55 14.65,115.55 14.65,117.65 16.25,117.65 16.25,118.85 56.99,118.85 57.67,118.57 57.95,117.89 57.95,81.15 57.69,79.65 56.96,78.31 55.75,74.85 56.96,71.39 ; 37 cut-outs
WMCU_VDD on TOP: 23.45,60.95 23.45,58.7 25,58.7 25,60.95
N1031635 on TOP: 6.75,112.9 6.75,117.6 8.05,117.6 8.05,115.5 9.95,115.5 9.95,117.6 12.75,117.6 12.75,115.7 14.45,115.7 14.45,115.1 14.65,115.1 14.65,115.7 14.65,117.6 15.95,117.6 15.95,112.9 ; 1 cut-out
N1031635 on BOTTOM, L2: 6.75,112.9 6.75,117.6 8.05,117.6 8.05,115.5 9.95,115.5 9.95,117.6 12.75,117.6 12.75,115.5 14.65,115.5 14.65,117.6 15.95,117.6 15.95,112.9
N2245591 on TOP (solid shape): 30.1,16.32 12.1,16.32 12.1,13.32 48.1,13.32 48.1,6.32 12.1,6.32 12.1,3.32 27.5,3.32 27.5,1.32 10.1,1.32 10.1,8.32 46.1,8.32 46.1,11.32 10.1,11.32 10.1,18.32 28.1,18.32 28.1,25.32 30.1,25.32
N2245591 on BOTTOM (solid shape): 30.1,16.3 12.1,16.3 12.1,13.3 48.1,13.3 48.1,6.3 12.1,6.3 12.1,3.3 27.5,3.3 27.5,1.3 10.1,1.3 10.1,8.3 46.1,8.3 46.1,11.3 10.1,11.3 10.1,18.3 28.1,18.3 28.1,25.3 30.1,25.3

Small or netless copper shapes (teardrops, artwork), in the pictures only: 4 on TOP

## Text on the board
Ref Des/Silkscreen Bottom: J1 | 1 | 10 | 21 | 30 | J3 | J4 | 31 | 40 | 11 | 20 | J2 | DIO23 | DIO22 | DIO24 | DIO2 | DIO3 | DIO1 | DIO25 | DIO27 | DIO28 | DIO29 | DIO30 | DIO26 | DIO7 | DIO6 | DIO20 | DIO19 | DIO18 | BPRST | DIO9 | DIO8 | DIO15 | DIO12 | DIO11 | LPRST | DIO13 | DIO14 | DIO10 | DIO21 | DIO4 | DIO5 | TMS | TCK | DIO16 | DIO17
User.Comments: WCS042 D | E1   Initial Version                                     2017-08-09  2017-08-09 | A    Production Release Version                          2017-10-20  2017-10-20 | C    Updated with new Energy Trace Circuit               2018-07-09  2018-07-09 | D    Production Release Version (Added CE Logo)          2018-10-10  2018-10-10 | B    Production Release Version (Added DustBin Symbol)   2018-01-04  2018-01-04 | PANEL DRAWING
Ref Des/Silkscreen Top: XDS110 Out | J1 | 10 | 1 | 21 | 30 | J3 | J4 | 40 | 31 | 20 | 11 | J2 | DIO3 | DIO22 | DIO2 | DIO24 | DIO23 | DIO13 | BTN-1 | DIO1 | DIO26 | DIO25 | DIO27 | DIO28 | DIO29 | DIO30 | DIO6 | Red: | LEDs | WCS042 D | Green: | DIO7 | CC-ANTENNA-DK | Mount for: | Target In | DIO20 | DIO19 | DIO18 | BPRST | BP | DIO14 | BTN-2 | LS_PWR | LP | Extern | Pwr | XDS110 | Power | DIO15 | DIO8 | DIO11 | LPRST | DIO9 | DIO12 | DIO10 | DIO21 | DIO4 | DIO5 | DIO17 | DIO16 | TMS | TCK | RXD<< | TXD>> | RST | TDO | TDI | SWO | LAUNCHXL-CC1312R1 | Rev:D
DIMENSION: V-CUT | 4. APPLY NON-CONDUCTIVE LPI SILKSCREEN OR EQUIVALENT PER THE ARTWORK. | CLASS 2 AND WORKMANSHIP SHALL CONFORM TO | PROCESS NOTES: | 3. SOLDERMASK ARTWORK HAS ZERO (0) OVERSIZED PADS. | 5. ALL VIAS ARE TENTED. | 2. PLATE ALL EXPOSED AREAS WITH ELECTROLESS NICKEL IMMERSION GOLD. | CURRENT REV. COLOR OF MASK TO BE RED. | THE LETTER CODE SHALL IDENTIFY THE MAUFACTURER AND IS DECIDED BY MFR. NO LOGOS OR OTHER IDENTIFIERS ARE ALLOWED | THE MARKING SHALL BE IN BOTTOM SILK SCREEN PRINT | RoHS/REACH CERTIFICATE OF CONFORMANCE SHALL BE DELIVERED WITH EACH LOT | 6. MAX. WARP & TWIST TO BE .0075 PER INCH. | 7. BOARD MUST BE ELECTRICALLY TESTED USING | 1. APPLY LPI SOLDERMASK OVER BARE COPPER (SMOBC), | LEAD FREE ASSEMBLY CAPABLE. BOARD MATERIAL | 8. 0.32MM TRACES ON LAYER 1 ARE 50 OHMS +/-10%. | 9. MANUFACTURER MARKING: TWO LETTER + YEAR + WEEK | 3. BOARD MATERIAL SHALL BE 180 Tg/340 Td ISOLA | 5. OVERALL BOARD THICKNESS TO BE1.6 MM | PROCESSES, MEASURED FROM COPPER TO COPPER. | 4. BOARD MATERIAL & CONSTRUCTION TO BE U.L. 94V-0 | 2. THE PWB SHALL BE FABRICATED TO IPC-6012, | 1. ALL DIMENSIONS ARE IN MM, UNLESS | FAB NOTES: | UL GUIDE NUMBER SHOULD BE MARKED ON THE FINISHED | OTHERWISE NOTED. | AND APPLIES AFTER ALL LAMINATION AND PLATING | SUPPLIED IPC-D-356 NETLIST. | IPC-A-600, CLASS 2. CURRENT REVISIONS. | SHALL MEET OR EXCEED IPC-4101B. | FR-370HR OR EQUIVALENT, RoHS COMPLIANT AND | THEY ARE REFERENCE TO LAYER 2 GROUND | SOLDERMASK SHALL CONFORM TO IPC-SM-840. CLASS H. | FABRICATION VENDOR IS ALLOWED TO ADJUST THE COMPONENT SOLDERMASK | APPROVED AND MARKED ON THE FINISHED BOARD. | BOARD. | NICKEL:100 MICRO-INCHES MIN. GOLD:2-8 MICROINCHES MIN. | COLOR: WHITE. | PADS TO MEET THEIR TOOLING REQUIREMENTS.
